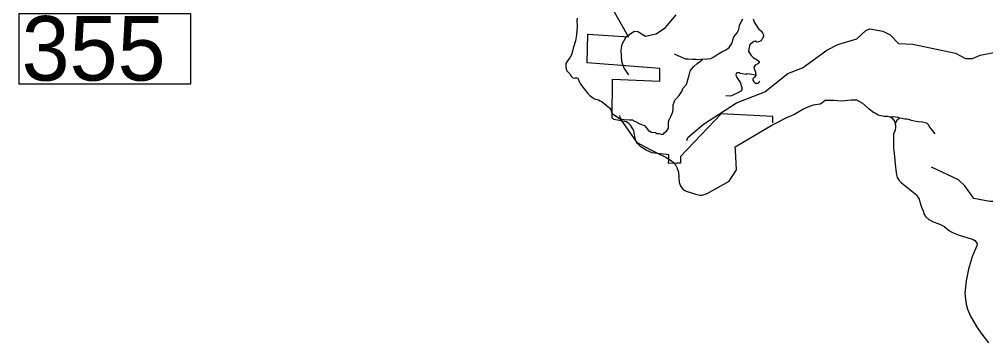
# Model space of a CAD drawing. Extents: x 1248224 to 1454986, y 825081 to 985870.
# Drawn here: x 1256105 to 1277074, y 855896 to 862920 of the extents above; entities that cross this region are included whole.
import ezdxf

# ---------------------------------------------------------------- set-up
doc = ezdxf.new("R2010")
doc.units = 0
for name, color, linetype in [('Exist Boundary Land Use Gamelands State NC Wildlife Resources Commission', 7, 'Continuous'), ('Exist Boundary Political CountyLine', 7, 'Continuous'), ('Exist Hydrographic Creek Single Shore', 7, 'Continuous'), ('Exist Hydrographic Misc Water Feature', 7, 'Continuous'), ('Exist Road Non-System Type 51', 7, 'Continuous'), ('Exist Road Secondary Structure Standard Bridge Number Label', 7, 'Continuous')]:
    doc.layers.add(name, color=color, linetype=linetype)

msp = doc.modelspace()

# ---------------------------------------------------------------- linework, layer by layer
at = {"layer": 'Exist Boundary Land Use Gamelands State NC Wildlife Resources Commission'}
msp.add_lwpolyline([(1272457, 860669), (1272455, 860777), (1272454, 860811), (1271331, 860870), (1270455, 859940), (1270450, 859795), (1270375, 859793), (1270195, 859787), (1270197, 859869), (1270200, 859975), (1269840, 860018), (1269723, 860071), (1269591, 860152), (1269518, 860221), (1269486, 860280), (1269463, 860372), (1269442, 860506), (1269369, 860617), (1269333, 860657), (1269275, 860691), (1269004, 860747), (1268981, 860762), (1268969, 860770), (1268969, 860776), (1268977, 861622), (1270004, 861579), (1270004, 861848), (1268429, 861971), (1268442, 862600), (1269327, 862536), (1268991, 863124)], dxfattribs=at)
at = {"layer": 'Exist Boundary Political CountyLine'}
for points in [[(1268211, 862945), (1268206, 862897), (1268213, 862764), (1268193, 862582), (1268173, 862454), (1268130, 862315), (1268084, 862151), (1268058, 862097), (1267984, 861997), (1267966, 861962), (1267964, 861884), (1267971, 861839), (1267989, 861804), (1268048, 861735), (1268083, 861686), (1268118, 861649), (1268153, 861643), (1268174, 861649), (1268200, 861650), (1268221, 861644), (1268235, 861626), (1268251, 861568), (1268280, 861508), (1268441, 861307), (1268482, 861264), (1268540, 861218), (1268589, 861191), (1268670, 861169), (1268709, 861151), (1268753, 861124), (1268842, 861058), (1268908, 860997), (1268932, 860966), (1268971, 860871), (1269152, 860748), (1269497, 860251), (1269795, 860092), (1270072, 859952), (1270117, 859933), (1270176, 859898), (1270275, 859828), (1270310, 859799), (1270344, 859758), (1270375, 859702), (1270397, 859643), (1270406, 859599), (1270426, 859377), (1270434, 859341), (1270450, 859301), (1270472, 859264), (1270518, 859218), (1270575, 859188), (1270807, 859114), (1270874, 859100), (1270920, 859102), (1271031, 859140), (1271510, 859407), (1271670, 859651), (1271644, 860069), (1271641, 860147), (1272431, 860618), (1272788, 860803), (1272834, 860818), (1272927, 860862), (1273110, 860967), (1273221, 861019), (1273335, 861060), (1273382, 861071), (1273483, 861087), (1273518, 861108), (1273591, 861161), (1273788, 861167), (1273947, 861150), (1274152, 861174), (1274269, 861171), (1274398, 861100), (1274526, 860991), (1274537, 860983), (1274582, 860947), (1274648, 860895), (1274676, 860887)], [(1274676, 860887), (1274742, 860848), (1274797, 860828), (1274875, 860816), (1274941, 860815), (1275001, 860801), (1275037, 860777), (1275068, 860744), (1275093, 860708), (1275108, 860667), (1275114, 860622), (1275115, 860567), (1275107, 860514), (1275076, 860432), (1275072, 860397), (1275077, 860115), (1275080, 860069), (1275095, 859938), (1275109, 859771), (1275129, 859586), (1275143, 859514), (1275155, 859485), (1275198, 859419), (1275248, 859365), (1275540, 859135), (1275571, 859104), (1275602, 859060), (1275628, 859012), (1275649, 858956), (1275682, 858837), (1275723, 858737), (1275734, 858698), (1275769, 858634), (1275844, 858571), (1275932, 858522), (1276058, 858480), (1276124, 858449), (1276173, 858418), (1276291, 858326), (1276356, 858290), (1276426, 858257), (1276497, 858231), (1276757, 858153), (1276804, 858135), (1276838, 858113), (1276868, 858080), (1276886, 858044), (1276886, 858037), (1276883, 857999), (1276787, 857782), (1276750, 857669)], [(1276750, 857669), (1276703, 857492), (1276653, 857241), (1276633, 857103), (1276625, 856972), (1276635, 856841), (1276650, 856732), (1276678, 856627), (1276748, 856475), (1276877, 856246), (1276980, 856085), (1276989, 856087), (1277016, 856053), (1277134, 855896)]]:
    msp.add_lwpolyline(points, dxfattribs=at)
at = {"layer": 'Exist Hydrographic Creek Single Shore'}
for points in [[(1270591, 860284), (1270609, 860352), (1270950, 860644), (1271670, 861109), (1272285, 861343), (1272778, 861740), (1273098, 861865), (1273625, 862252), (1273869, 862371), (1274281, 862494), (1274477, 862674), (1274561, 862715), (1274844, 862664), (1275000, 862585), (1275179, 862391), (1275496, 862381), (1276416, 862186), (1276639, 862070), (1276789, 862067), (1276957, 862139), (1277251, 862199)], [(1282509, 857552), (1282319, 857723), (1282253, 857889), (1282224, 858099), (1282153, 858417), (1282020, 858804), (1281932, 858914), (1281822, 858883), (1281686, 858778), (1281451, 858684), (1281367, 858686), (1280375, 859053), (1280060, 859093), (1279451, 859092), (1278339, 858960), (1277163, 858964), (1276814, 859030), (1276621, 859303), (1276482, 859430), (1275897, 859705)]]:
    msp.add_lwpolyline(points, dxfattribs=at)
at = {"layer": 'Exist Hydrographic Misc Water Feature'}
msp.add_lwpolyline([(1269334, 861717), (1269229, 861860), (1269182, 862002), (1269163, 862246), (1269183, 862380), (1269270, 862536), (1269448, 862664), (1269523, 862655), (1269696, 862550), (1269922, 862602), (1270126, 862739), (1270358, 863016)], dxfattribs=at)
at = {"layer": 'Exist Road Non-System Type 51'}
for points in [[(1270927, 862057), (1271036, 862059), (1271112, 862066), (1271174, 862104), (1271260, 862161), (1271370, 862227), (1271430, 862252), (1271506, 862305), (1271538, 862352), (1271566, 862397), (1271606, 862541), (1271679, 862626), (1271719, 862701), (1271731, 862784), (1271769, 862864), (1271802, 862932)], [(1272027, 862931), (1272049, 862858), (1272092, 862793), (1272117, 862758), (1272147, 862713), (1272167, 862695), (1272225, 862645), (1272245, 862592), (1272258, 862559), (1272235, 862507), (1272200, 862449), (1272147, 862429), (1272105, 862426), (1272080, 862447), (1272049, 862441), (1272017, 862419), (1271957, 862366), (1271942, 862311), (1271929, 862218), (1271989, 862132), (1272030, 862089), (1272117, 862041), (1272160, 862004), (1272160, 861991), (1272142, 861964), (1272127, 861951), (1272072, 861921), (1272045, 861883), (1272050, 861853), (1272080, 861773), (1272090, 861710), (1272057, 861660), (1272025, 861627), (1272025, 861620), (1272025, 861595), (1272042, 861559), (1272072, 861532), (1272140, 861534), (1272157, 861552), (1272175, 861580)], [(1269129, 860829), (1269139, 860789), (1269149, 860771), (1269154, 860766), (1269179, 860754), (1269227, 860741), (1269352, 860734), (1269410, 860736), (1269425, 860723), (1269475, 860703), (1269540, 860666), (1269621, 860628), (1269671, 860613), (1269708, 860573), (1269751, 860515), (1269821, 860472), (1269909, 860460), (1269937, 860442), (1269987, 860442), (1270019, 860432), (1270050, 860420), (1270082, 860425), (1270085, 860432), (1270100, 860457), (1270157, 860498), (1270190, 860555), (1270193, 860618), (1270195, 860691), (1270208, 860736), (1270245, 860811), (1270288, 860912), (1270293, 860975), (1270293, 861065), (1270305, 861098), (1270330, 861160), (1270421, 861266), (1270483, 861352), (1270505, 861415), (1270560, 861480), (1270583, 861505), (1270613, 861608), (1270638, 861706), (1270663, 861794), (1270688, 861834), (1270741, 861894), (1270811, 861959), (1270887, 862012), (1270917, 862035), (1270927, 862057)], [(1270927, 862057), (1270839, 862037), (1270829, 862037), (1270794, 862045), (1270714, 862050), (1270618, 862055), (1270566, 862055), (1270405, 862123), (1270322, 862160)], [(1272090, 861710), (1271947, 861730), (1271899, 861735), (1271879, 861723), (1271794, 861733), (1271746, 861745), (1271724, 861758), (1271673, 861758), (1271658, 861740), (1271651, 861713), (1271671, 861655), (1271718, 861590), (1271746, 861554), (1271786, 861436), (1271781, 861389), (1271764, 861362), (1271694, 861324), (1271586, 861269), (1271556, 861254), (1271505, 861251), (1271435, 861254)], [(1275976, 860431), (1275893, 860542), (1275861, 860574), (1275836, 860626), (1275797, 860661), (1275698, 860685), (1275617, 860690), (1275526, 860710), (1275462, 860725), (1275407, 860747), (1275358, 860754), (1275319, 860752), (1275265, 860762), (1275196, 860769), (1275178, 860789), (1275119, 860794), (1275055, 860801), (1275014, 860793)], [(1275112, 860635), (1275132, 860693), (1275159, 860742), (1275196, 860769)]]:
    msp.add_lwpolyline(points, dxfattribs=at)
at = {"layer": 'Exist Road Secondary Structure Standard Bridge Number Label'}
msp.add_lwpolyline([(1256105, 863048), (1259821, 863048), (1259821, 861511), (1256105, 861511)], close=True, dxfattribs=at)

# ---------------------------------------------------------------- texts
msp.add_text('355', height=1400, dxfattribs=at).set_placement((1256155, 861590))

doc.saveas('drawing.dxf')
